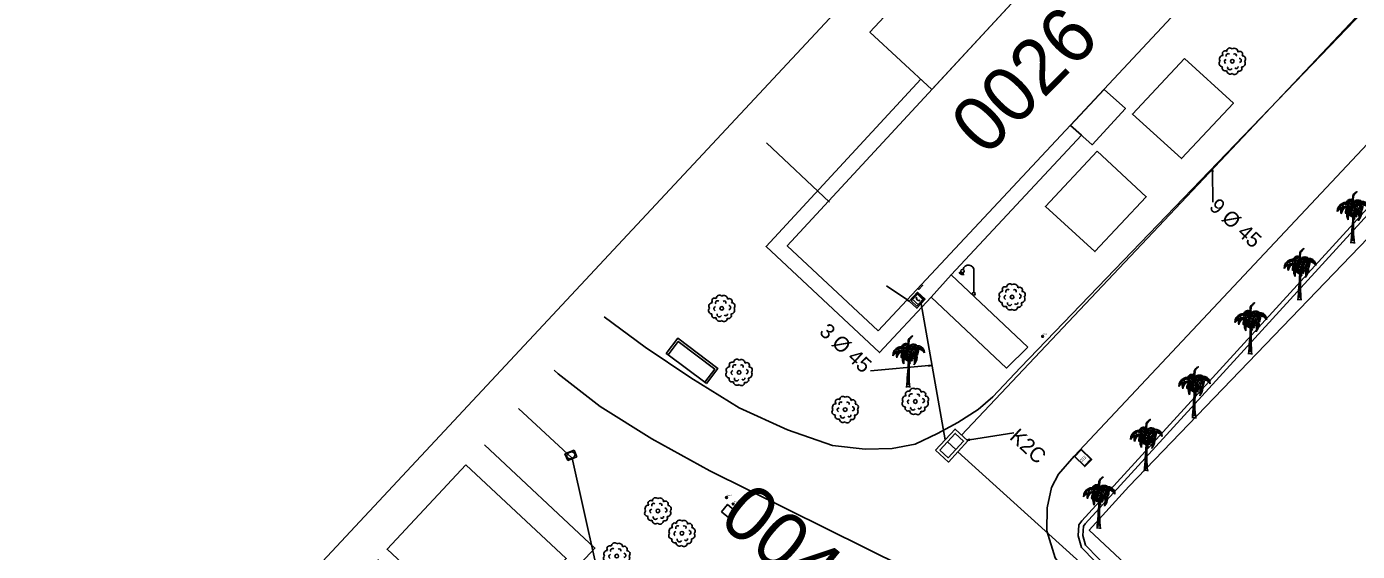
# Model space of a CAD drawing. Extents: x 343997 to 344255, y 298512 to 298767.
# Drawn here: x 343997.3 to 344085.4, y 298682.3 to 298717.1 of the extents above; entities that cross this region are included whole.
import ezdxf

# ---------------------------------------------------------------- set-up
doc = ezdxf.new("R2010")
doc.units = 0
for name, color, linetype in [('Default', 7, 'Continuous'), ('DH_CADRE -CARTOUCHE', 7, 'Continuous'), ('DH_CADRE-CARTOUCHE', 7, 'Continuous'), ('DH_CADRE-CARTOUCHE-NORD', 7, 'Continuous'), ('DH_TEXTE', 7, 'Continuous'), ('DIR-Projet VRD1', 7, 'Continuous'), ('EL-coffret', 7, 'Continuous'), ('GO_DALLE', 7, 'Continuous'), ('O-Projet New VRD', 7, 'Continuous'), ('PC_REBAR', 7, 'Continuous'), ('PS_HIDDEN', 7, 'Continuous'), ('PS_MID', 7, 'Continuous'), ('PS_PLATE', 7, 'Continuous'), ('RES_EAU', 7, 'Continuous'), ('RES_EAU PLUVIALE', 7, 'Continuous'), ('RES_ELECTRICITE', 7, 'Continuous')]:
    doc.layers.add(name, color=color, linetype=linetype)

# ---------------------------------------------------------------- blocks, each defined once
blk = doc.blocks.new('PTT3')
at = {"layer": 'Default'}
for p, q in [((0, 0.1), (0.1, 0.1)), ((0, 0), (0, 0.1)), ((0.1, 0), (0, 0)), ((0.1, 0.1), (0.1, 0))]:
    blk.add_line(p, q, dxfattribs=at)
for centre, radius, start, end in [((0.05, 0.07), 0.00417, 0, 180), ((0.05, 0.07), 0.00417, 180, 0), ((0.05, 0.029), 0.00417, 0, 180), ((0.05, 0.029), 0.00417, 180, 0), ((0.04, 0.049), 0.0229, 297.2754, 62.7246)]:
    blk.add_arc(centre, radius, start, end, dxfattribs=at)
blk = doc.blocks.new('REG_INC')
at = {"layer": 'Default'}
for p, q in [((0, 0.1), (0.1, 0.1)), ((0, 0), (0, 0.1)), ((0.1, 0), (0, 0)), ((0.1, 0.1), (0.1, 0))]:
    blk.add_line(p, q, dxfattribs=at)
for start, end in [(135.0055, 180.0055), (180.0066, 225.0066), (90.0058, 135.0058), (225.0069, 270.0069), (45.0069, 90.0069), (270.0058, 315.0058), (0.0066, 45.0066), (315.0055, 0.0055)]:
    blk.add_arc((0.05, 0.05), 0.044, start, end, dxfattribs=at)
blk = doc.blocks.new('RES_ELECTRICITE')
at = {"layer": 'RES_ELECTRICITE'}
for points in [[(0, 0), (0, 0.1), (0.1, 0.1), (0.1, 0)], [(0.005, 0.005), (0.005, 0.095), (0.095, 0.095), (0.095, 0.005)]]:
    blk.add_lwpolyline(points, close=True, dxfattribs=at)
blk.add_text('EEC', height=0.02, dxfattribs=at).set_placement((0.0237, 0.046))
blk = doc.blocks.new('BC2')
at = {"layer": 'Default'}
blk.add_line((-0.011, -0.011), (0.011, 0.011), dxfattribs=at)
blk.add_circle((0, 0), 0.015, dxfattribs=at)
blk.add_text('EAU', height=0.0227, dxfattribs=at).set_placement((0.017, 0.026))
blk = doc.blocks.new('EDF1')
at = {"layer": 'Default'}
for points in [[(-0.0855, 0.1462), (-0.0985, 0.1373)], [(-0.083, 0.1422), (-0.0931, 0.1303)], [(-0.0793, 0.1397), (-0.086, 0.1257)], [(-0.0753, 0.1388), (-0.0781, 0.1235)], [(-0.0701, 0.14), (-0.0684, 0.1241)], [(0, 0.01), (0, 0.15)]]:
    blk.add_lwpolyline(points, dxfattribs=at)
for centre, radius in [((-0.075, 0.15), 0.0112), ((0, 0), 0.01)]:
    blk.add_circle(centre, radius, dxfattribs=at)
blk.add_arc((-0.035, 0.155), 0.0354, 351.8699, 171.8699, dxfattribs=at)
blk = doc.blocks.new('COCO')
at = {"layer": 'Default'}
for p, q in [((-0.0046, 0.0891), (0.0052, 0.0927)), ((0.0054, 0.0998), (-0.0041, 0.0985)), ((-0.0037, 0.106), (0.0056, 0.1071)), ((0.0058, 0.114), (-0.003, 0.1162)), ((-0.0026, 0.1226), (0.0061, 0.1212)), ((0.0046, 0.0033), (-0.0076, 0.0051)), ((-0.0073, 0.017), (0.0045, 0.0209)), ((0.0045, 0.0292), (-0.007, 0.0288)), ((-0.0068, 0.0371), (0.0045, 0.0374)), ((0.0045, 0.047), (-0.0065, 0.0453)), ((-0.0062, 0.0537), (0.0046, 0.0552)), ((0.0047, 0.0655), (-0.0058, 0.0642))]:
    blk.add_line(p, q, dxfattribs=at)
for points in [[(-0.0487, 0.268), (-0.0386, 0.265)], [(0.0029, 0.2551), (-0.0016, 0.2896), (0.0002, 0.3125), (0.0059, 0.3241), (0.0173, 0.3348), (0.0189, 0.3356), (0.0282, 0.3415), (0.0266, 0.3373), (0.02, 0.3318), (0.0143, 0.3247), (0.0093, 0.32), (0.0081, 0.3165), (0.0057, 0.3133), (0.0057, 0.3099), (0.006, 0.3037), (0.0039, 0.2989), (0.0039, 0.2944), (0.0049, 0.2877), (0.0037, 0.2841), (0.0013, 0.2736)], [(0.0013, 0.2736), (0.0036, 0.2813), (0.0046, 0.2746)], [(0.0196, 0.2687), (0.0323, 0.2715)], [(0.0283, 0.2765), (0.0331, 0.2786)], [(-0.0746, 0.2559), (-0.0864, 0.2483)], [(-0.077, 0.2413), (-0.0836, 0.2333)], [(-0.0607, 0.2534), (-0.0704, 0.2443)], [(-0.0636, 0.2639), (-0.0541, 0.2608)], [(-0.0421, 0.258), (-0.0503, 0.2523)], [(-0.0183, 0.2493), (-0.0348, 0.2417), (-0.0401, 0.2307), (-0.0448, 0.2203), (-0.0471, 0.2086), (-0.0474, 0.2023), (-0.0466, 0.1973), (-0.0455, 0.2054), (-0.0451, 0.2146), (-0.0387, 0.2292), (-0.0351, 0.2354), (-0.0284, 0.2404), (-0.0233, 0.2445), (-0.0012, 0.2495)], [(-0.0256, 0.2553), (-0.0385, 0.2508)], [(-0.0321, 0.1997), (-0.0364, 0.19)], [(-0.0276, 0.2151), (-0.0329, 0.2086)], [(-0.0203, 0.2314), (-0.0274, 0.2258)], [(-0.023, 0.2152), (-0.0237, 0.2043)], [(-0.0161, 0.2218), (-0.0158, 0.2122)], [(-0.0059, 0.2024), (-0.0083, 0.1998)], [(-0.004, 0.2247), (-0.0081, 0.2179)], [(0.0015, 0.2414), (-0.0056, 0.2352)], [(-0.0025, 0.2032), (0.0002, 0.1954)], [(0.0022, 0.224), (0.0043, 0.213)], [(0.0081, 0.2404), (0.0106, 0.2299)], [(0.0133, 0.2608), (0.0185, 0.2634)], [(0.0385, 0.237), (0.0469, 0.2254)], [(0.0473, 0.2115), (0.0509, 0.2012)], [(-0.0055, 0.0716), (0.0048, 0.0717), (0.0049, 0.0787), (-0.0051, 0.0795)]]:
    blk.add_lwpolyline(points, dxfattribs=at)
for centre, radius in [((-0.0187, 0.1897), 0.00384), ((-0.0144, 0.1978), 0.00616), ((-0.0124, 0.1896), 0.00376), ((-0.011, 0.184), 0.00471), ((0.0134, 0.1862), 0.00549), ((0.0208, 0.1822), 0.00626), ((0.0254, 0.1938), 0.00628)]:
    blk.add_circle(centre, radius, dxfattribs=at)
for centre, radius, start, end in [((-0.0427, 0.2113), 0.0595, 43.61211, 181.46245), ((-0.0123, 0.259), 0.0323, 122.34745, 158.76357), ((-0.0199, 0.2618), 0.0238, 4.52184, 154.10099), ((-0.0252, 0.2556), 0.0231, 4.24411, 134.21032), ((-0.016, 0.2647), 0.0255, 21.08609, 122.34745), ((0.0376, 0.2508), 0.0372, 113.76809, 175.33093), ((0.0376, 0.2508), 0.0372, 113.76809, 175.33093), ((0.0418, 0.2527), 0.0326, 97.12484, 183.95116), ((0.1025, 0.2053), 0.0958, 126.68582, 153.16638), ((0.0618, 0.2316), 0.0451, 356.16265, 159.00089), ((0.0609, 0.2187), 0.0468, 12.10772, 148.31459), ((0.0344, 0.2407), 0.0451, 69.08173, 104.86204), ((-0.1005, 0.1577), 0.1786, 37.56679, 40.51564), ((-0.0254, 0.228), 0.0869, 28.47252, 37.09653), ((0.0493, 0.2767), 0.00679, 35.32051, 126.68582), ((-0.0054, 0.2379), 0.0738, 25.81944, 35.32051), ((-0.0291, 0.1543), 0.0918, 76.73894, 142.80251), ((-0.038, 0.1964), 0.0648, 57.91917, 166.62012), ((-0.03, 0.212), 0.0482, 151.13313, 199.59422), ((-0.0196, 0.1874), 0.0565, 78.51401, 171.35044), ((-0.032, 0.2055), 0.0433, 119.08336, 188.76207), ((0.0362, 0.1922), 0.0754, 136.71129, 208.82208), ((0.0551, 0.179), 0.0879, 137.73301, 194.37159), ((0.0649, 0.1599), 0.0949, 145.51456, 182.45279), ((0.062, 0.2159), 0.0753, 153.08677, 230.11243), ((0.0659, 0.2068), 0.0718, 142.35537, 222.27942), ((-0.0007, 0.2465), 0.00563, 81.74752, 144.30354), ((-0.0279, 0.1637), 0.0281, 2.14987, 36.63246), ((-0.0189, 0.121), 0.1324, 71.37146, 81.74752), ((0.0294, 0.2595), 0.0256, 198.67654, 199.76266), ((0.0963, 0.1939), 0.09, 143.98655, 203.42885), ((0.0544, 0.1816), 0.0474, 137.19533, 172.89867), ((0.0308, 0.2014), 0.0226, 121.42967, 182.28997), ((2.7302, 0.0106), 2.7266, 175.47911, 176.55971), ((0.0311, 0.2152), 0.0219, 141.85595, 191.51747), ((0.0372, 0.1847), 0.0277, 133.59561, 173.48701), ((0.0808, 0.1542), 0.0777, 142.23578, 156.28002), ((0.0242, 0.1964), 0.0147, 110.97274, 165.97557), ((0.0404, 0.1878), 0.0354, 125.05854, 146.38926), ((0.0398, 0.2098), 0.0301, 136.45687, 162.06855), ((0.0357, 0.2084), 0.0244, 133.11836, 172.75341), ((-0.0759, 0.1958), 0.0922, 344.85055, 15.89877), ((-0.0404, 0.2045), 0.0619, 329.46655, 26.67931), ((-0.0289, 0.211), 0.0564, 317.8279, 12.33856), ((0.059, 0.2015), 0.0548, 29.56544, 139.35171), ((-0.0543, 0.1744), 0.096, 344.8781, 41.14605), ((-0.0341, 0.19), 0.0828, 46.97669, 50.12313), ((-0.0157, 0.2027), 0.074, 51.24751, 54.5217), ((-0.0341, 0.19), 0.0828, 334.06866, 41.194), ((-0.0157, 0.2027), 0.074, 315.14717, 39.02392), ((-0.1704, 0.1849), 0.2327, 7.59784, 16.36658), ((-0.0254, 0.228), 0.0869, 350.88829, 14.70633), ((-0.0482, 0.2552), 0.1161, 339.35966, 356.59253), ((-8.5428, 0.7294), 8.5622, 355.11326, 356.26352), ((-0.0265, 0.1505), 0.0316, 339.99973, 25.72283), ((0.0199, 0.166), 0.0176, 166.9443, 185.59662)]:
    blk.add_arc(centre, radius, start, end, dxfattribs=at)
blk.add_ellipse((2.7425, 0.0272), major_axis=(-2.7371, 0.0966), ratio=0.529859, start_param=6.255729, end_param=6.369141, dxfattribs=at)
blk = doc.blocks.new('ARB1')
at = {"layer": 'Default'}
blk.add_circle((0, 0), 0.0122, dxfattribs=at)
for centre, radius, start, end in [((-0.0613, 0.0139), 0.0241, 88.45835, 215.19284), ((-0.0471, 0.0503), 0.0183, 53.95544, 222.20655), ((-0.0373, -0.0024), 0.0149, 103.70924, 242.34652), ((-0.0276, 0.037), 0.0134, 52.43963, 209.54959), ((-0.0153, 0.0664), 0.0211, 43.69255, 183.5969), ((0.0139, 0.0613), 0.0241, 358.45835, 125.19284), ((0.0164, 0.038), 0.0112, 330.58954, 133.71274), ((0.0501, 0.0468), 0.0183, 325.14445, 131.01755), ((0.0458, 0.0052), 0.0137, 276.62143, 88.96702), ((0.0613, -0.0139), 0.0241, 268.45835, 35.19284), ((0.0664, 0.0153), 0.0211, 313.69255, 93.5969), ((-0.0664, -0.0153), 0.0211, 133.69255, 273.5969), ((-0.0478, -0.0443), 0.019, 155.22426, 300.93774), ((-0.0139, -0.0613), 0.0241, 178.45835, 305.19284), ((-0.0163, -0.042), 0.0148, 159.53711, 338.16632), ((0.0153, -0.0664), 0.0211, 223.69255, 3.5969), ((0.0271, -0.038), 0.0112, 210.58954, 13.71274), ((0.0448, -0.0483), 0.0188, 243.13234, 33.02965)]:
    blk.add_arc(centre, radius, start, end, dxfattribs=at)

msp = doc.modelspace()

# ---------------------------------------------------------------- linework, layer by layer
at = {"layer": 'DH_CADRE -CARTOUCHE'}
for points in [[(343997.309, 298660.673), (344147.183, 298520.807), (344245.09, 298625.72), (344095.215, 298765.586)], [(344026.391, 298688.063), (344021.173, 298682.472), (344027.812, 298676.264), (344033.029, 298681.855)]]:
    msp.add_lwpolyline(points, close=True, dxfattribs=at)
at = {"layer": 'DH_CADRE-CARTOUCHE'}
for points in [[(344035.538, 298697.865), (344038.262, 298695.856), (344041.267, 298693.813), (344044.479, 298691.842), (344047.664, 298690.365), (344050.648, 298689.339), (344052.822, 298689.099), (344054.599, 298689.128), (344056.124, 298689.428), (344057.609, 298690.129), (344058.956, 298690.85), (344060.299, 298691.725), (344061.274, 298692.556), (344063.092, 298694.498), (344091.5, 298724.03), (344099.786, 298732.889), (344115.711, 298749.674), (344119.028, 298753.296)], [(344091.665, 298656.941), (344066.817, 298679.859), (344065.379, 298681.895), (344064.833, 298683.692), (344064.865, 298685.2), (344065.154, 298686.548), (344065.609, 298687.44), (344066.641, 298688.625), (344090.832, 298714.382)], [(344032.232, 298694.322), (344032.494, 298694.078), (344035.262, 298691.929), (344038.684, 298689.77), (344042.541, 298687.653), (344055.386, 298681.278), (344062.722, 298673.608), (344079.116, 298659.278), (344094.724, 298644.749)]]:
    msp.add_lwpolyline(points, dxfattribs=at)
at = {"layer": 'DH_CADRE-CARTOUCHE-NORD'}
msp.add_line((344046.28, 298709.375), (344050.455, 298705.457), dxfattribs=at)
msp.add_lwpolyline([(344029.869, 298691.79), (344033.417, 298688.488), (344035.683, 298678.309)], dxfattribs=at)
at = {"layer": 'DIR-Projet VRD1'}
msp.add_line((344058.942, 298688.92), (344083.424, 298666.786), dxfattribs=at)
msp.add_lwpolyline([(344102.789, 298736.23), (344059.183, 298690.031)], dxfattribs=at)
at = {"layer": 'EL-coffret'}
msp.add_lwpolyline([(344056.54, 298700.006), (344056.613, 298699.939), (344056.362, 298699.667), (344056.29, 298699.734)], close=True, dxfattribs=at)
at = {"layer": 'GO_DALLE'}
msp.add_line((344057.227, 298712.914), (344053.123, 298716.708), dxfattribs=at)
for points in [[(344073.957, 298714.953), (344077.191, 298712), (344073.752, 298708.338), (344070.501, 298711.277), (344073.957, 298714.953)], [(344056.494, 298713.592), (344046.252, 298702.513), (344053.766, 298695.488), (344057.19, 298699.164), (344058.498, 298700.644), (344067.125, 298709.889), (344066.413, 298710.529)], [(344066.413, 298710.529), (344067.838, 298709.25), (344070.039, 298711.658), (344068.641, 298712.909), (344066.413, 298710.529)], [(344063.573, 298695.847), (344062.158, 298694.46), (344057.19, 298699.164), (344058.498, 298700.644), (344063.573, 298695.847)], [(344020.546, 298681.8), (344027.856, 298674.963), (344034.929, 298682.543), (344027.611, 298689.371)]]:
    msp.add_lwpolyline(points, dxfattribs=at)
for points in [[(344068.161, 298708.816), (344064.747, 298705.157), (344068.02, 298702.18), (344071.418, 298705.806)], [(344039.77, 298695.348), (344042.193, 298693.529), (344042.856, 298694.402), (344040.441, 298696.226)], [(344043.302, 298684.953), (344043.703, 298685.435), (344044.152, 298685.062), (344043.762, 298684.57)]]:
    msp.add_lwpolyline(points, close=True, dxfattribs=at)
at = {"layer": 'O-Projet New VRD'}
for p, q in [((344056.512, 298698.721), (344058.116, 298689.722)), ((344058.263, 298689.586), (344058.815, 298689.078))]:
    msp.add_line(p, q, dxfattribs=at)
for points in [[(344075.772, 298707.468), (344075.8, 298707.648), (344075.832, 298707.468)], [(344055.592, 298699.025), (344055.725, 298698.9), (344055.559, 298698.976)], [(344057.02, 298694.657), (344057.202, 298694.643), (344057.025, 298694.597)], [(344057.473, 298689.023), (344058.76, 298690.421), (344059.606, 298689.642), (344058.319, 298688.244)], [(344057.755, 298689.034), (344058.771, 298690.138), (344059.323, 298689.63), (344058.307, 298688.526)], [(344059.731, 298689.692), (344059.549, 298689.695), (344059.722, 298689.752)]]:
    msp.add_lwpolyline(points, close=True, dxfattribs=at)
for points in [[(344075.802, 298707.468), (344075.824, 298705.458)], [(344055.576, 298699.001), (344054.217, 298699.909)], [(344055.727, 298698.902), (344056.267, 298699.489), (344056.783, 298699.015), (344056.241, 298698.426), (344055.725, 298698.9)], [(344055.865, 298698.91), (344056.271, 298699.351), (344056.639, 298699.012), (344056.233, 298698.571), (344055.865, 298698.91)], [(344057.022, 298694.627), (344053.171, 298694.277)], [(344059.727, 298689.722), (344062.657, 298690.171)]]:
    msp.add_lwpolyline(points, dxfattribs=at)
at = {"layer": 'PC_REBAR'}
msp.add_lwpolyline([(344115.386, 298697.034), (344095.685, 298715.142), (344067.379, 298684.161), (344067.261, 298683.991), (344067.218, 298683.388), (344067.403, 298682.745), (344071.702, 298678.318), (344092.045, 298659.877), (344116.981, 298686.713), (344117.24, 298686.552), (344092.063, 298659.455), (344071.494, 298678.102), (344067.135, 298682.59), (344066.915, 298683.356), (344066.967, 298684.094), (344067.145, 298684.349), (344095.667, 298715.566), (344115.589, 298697.255)], close=True, dxfattribs=at)
msp.add_lwpolyline([(344091.233, 298661.951), (344078.543, 298673.539), (344067.651, 298683.727), (344070.267, 298686.633), (344094.013, 298711.291), (344094.723, 298711.636), (344095.462, 298711.65), (344096.516, 298711.35), (344098.055, 298710.152), (344102.625, 298705.772), (344106.459, 298702.051), (344111.683, 298696.937), (344113.434, 298695.237), (344113.122, 298693.176), (344113.133, 298690.945), (344113.53, 298689.467), (344114.335, 298687.988), (344114.712, 298687.466), (344091.233, 298661.951)], dxfattribs=at)
at = {"layer": 'PS_HIDDEN'}
msp.add_lwpolyline([(344067.036, 298731.616), (344053.123, 298716.708), (344057.227, 298712.914), (344071.037, 298727.852)], close=True, dxfattribs=at)
at = {"layer": 'PS_MID'}
msp.add_line((344057.227, 298712.914), (344053.123, 298716.708), dxfattribs=at)
at = {"layer": 'PS_PLATE'}
for points in [[(344053.664, 298696.925), (344047.653, 298702.558), (344071.037, 298727.852), (344077.207, 298722.133)], [(344042.312, 298693.439), (344043.067, 298694.431), (344040.413, 298696.435), (344039.651, 298695.439), (344039.77, 298695.348), (344040.441, 298696.226), (344042.856, 298694.402), (344042.193, 298693.529)]]:
    msp.add_lwpolyline(points, close=True, dxfattribs=at)

# ---------------------------------------------------------------- block references
at = {"layer": 'GO_DALLE', "xscale": 5.072243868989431, "yscale": 6.2616295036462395, "rotation": -131.69421}
msp.add_blockref('PTT3', (344056.238, 298699.419), dxfattribs=at)
at = {"layer": 'PC_REBAR', "xscale": 10, "yscale": 10}
for name, p in [('ARB1', (344077.115, 298714.782)), ('COCO', (344085.085, 298702.727)), ('COCO', (344081.572, 298698.962)), ('ARB1', (344062.539, 298699.168)), ('ARB1', (344043.322, 298698.418)), ('COCO', (344078.305, 298695.374)), ('COCO', (344055.666, 298693.183)), ('ARB1', (344044.47, 298694.177)), ('COCO', (344074.587, 298691.14)), ('ARB1', (344056.136, 298692.251)), ('ARB1', (344051.49, 298691.717)), ('COCO', (344071.402, 298687.647)), ('COCO', (344068.279, 298683.837)), ('ARB1', (344039.091, 298685.008)), ('ARB1', (344040.681, 298683.525)), ('ARB1', (344036.374, 298682.011))]:
    msp.add_blockref(name, p, dxfattribs=at)
at = {"layer": 'RES_EAU', "xscale": 4, "yscale": 4}
for p in [(344064.56, 298696.561), (344043.639, 298685.895), (344044.077, 298685.463)]:
    msp.add_blockref('BC2', p, dxfattribs=at)
at = {"layer": 'RES_EAU PLUVIALE', "xscale": 6.5304499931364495, "yscale": 4.871257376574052, "rotation": 21.944339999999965}
msp.add_blockref('REG_INC', (344033.125, 298688.339), dxfattribs=at)
at = {"layer": 'RES_ELECTRICITE', "xscale": 10, "yscale": 10}
msp.add_blockref('EDF1', (344060.005, 298699.384), dxfattribs=at)
at = {"layer": 'RES_ELECTRICITE', "xscale": 6.68200293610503, "yscale": 9.825932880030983, "rotation": -134.09487000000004}
msp.add_blockref('RES_ELECTRICITE', (344067.106, 298689.104), dxfattribs=at)

# ---------------------------------------------------------------- texts
at = {"layer": 'DH_TEXTE'}
for s, rotation, p in [('0026', 45.36652, (344060.789, 298708.397)), ('0049', 320.36653, (344042.992, 298684.271))]:
    msp.add_text(s, height=3.662, rotation=rotation, dxfattribs=at).set_placement(p)
at = {"layer": 'O-Projet New VRD'}
for s, p in [('9 Ø 45', (344075.522, 298705.062)), ('3 Ø 45', (344049.714, 298696.786)), ('K2C', (344062.308, 298689.813))]:
    msp.add_text(s, height=1.0003, rotation=317.36723, dxfattribs=at).set_placement(p)

doc.saveas('drawing.dxf')
